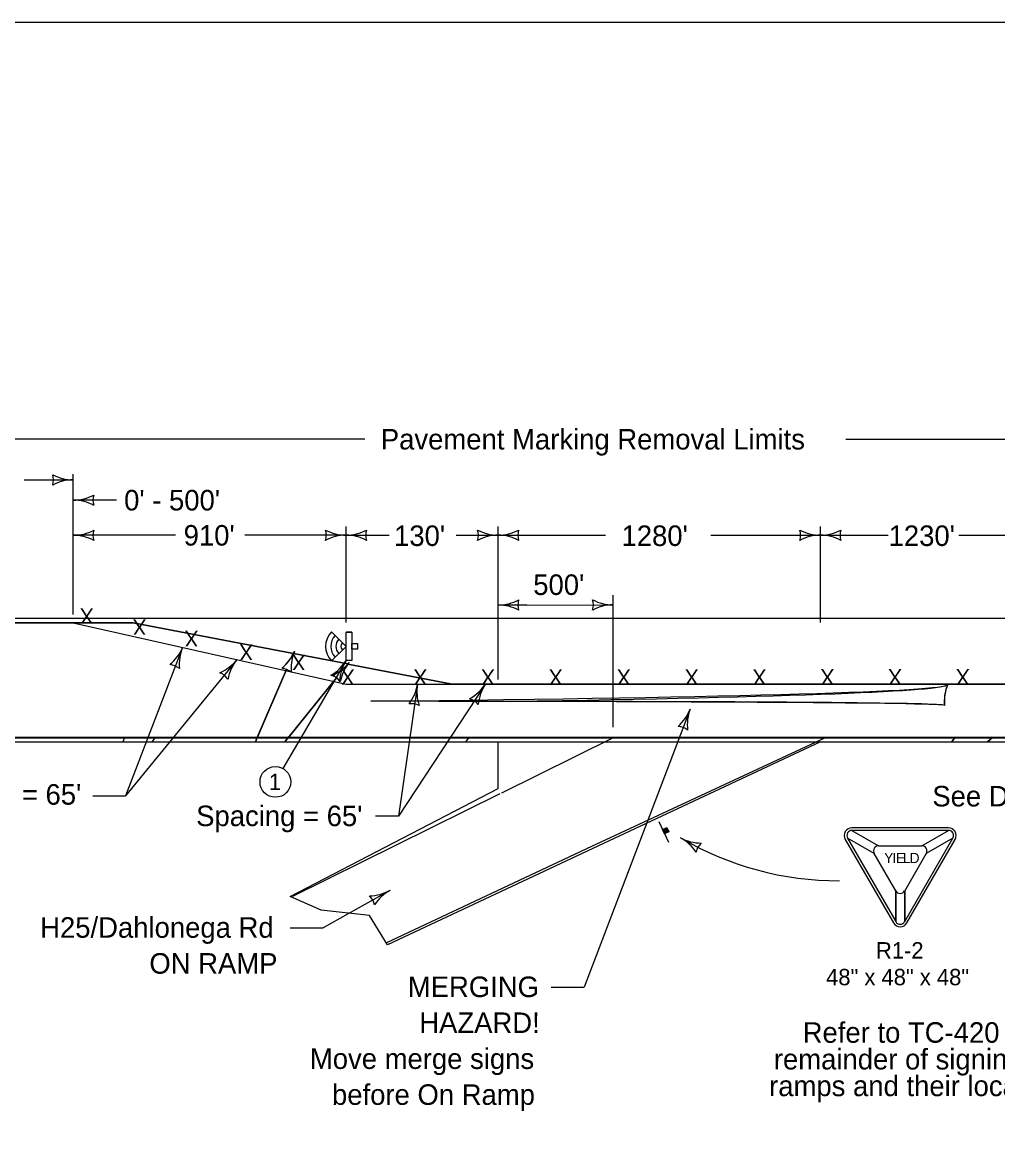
# Model space of a CAD drawing. Extents: x 10133 to 2270741, y 5363 to 1733450.
# Drawn here: x 25709 to 26660, y 8863 to 9944 of the extents above; entities that cross this region are included whole.
import ezdxf

# ---------------------------------------------------------------- set-up
doc = ezdxf.new("R2010")
doc.units = 0
for name, color, linetype in [('dsnNonPlotable', 7, 'Continuous'), ('dsnShtPlotShapeBatchPrint', 7, 'Continuous'), ('dsnStdBlockModified', 7, 'Continuous'), ('dsnStdBorder', 7, 'Continuous'), ('Level 12', 7, 'Continuous'), ('Level 2', 7, 'Continuous'), ('SheetBorder', 7, 'Continuous')]:
    doc.layers.add(name, color=color, linetype=linetype)

msp = doc.modelspace()

# ---------------------------------------------------------------- linework, layer by layer
at = {"layer": 'dsnNonPlotable'}
for p, q in [((24562.7, 9359.1), (25758.9, 9359.1)), ((25758.9, 9359.1), (26024.7, 9299.3)), ((26024.7, 9299.3), (26682.4, 9299.3)), ((24554.7, 9247), (26172.9, 9247)), ((26172.9, 9247), (26285, 9247)), ((26285, 9247), (26176.2, 9193.1)), ((26491.2, 9247), (26681.3, 9247)), ((26174.7, 9192.4), (25972.7, 9092.3))]:
    msp.add_line(p, q, dxfattribs=at)
msp.add_lwpolyline([(26063.8, 9047.3), (26264.1, 9141.5), (26491.2, 9247)], dxfattribs=at)
at = {"layer": 'dsnShtPlotShapeBatchPrint'}
msp.add_circle((25955.9, 9204), 15, dxfattribs=at)
at = {"layer": 'dsnStdBlockModified'}
for p, q in [((26010.5, 9350.1), (26024.7, 9336)), ((26030.3, 9349.7), (26024.7, 9349.7)), ((26024.7, 9336), (26010.5, 9321.8)), ((26030.3, 9322.2), (26024.7, 9322.2)), ((26329.3, 9165.5), (26338.8, 9145.3)), ((26335.3, 9153.6), (26333.3, 9157.7)), ((26333.6, 9157.8), (26335.5, 9153.7)), ((26335.7, 9153.8), (26333.8, 9157.9)), ((26333.9, 9158), (26335.9, 9153.9)), ((26336, 9153.9), (26334.1, 9158)), ((26334.3, 9158.1), (26336.2, 9154)), ((26336.4, 9154.1), (26334.5, 9158.2)), ((26334.7, 9158.3), (26336.6, 9154.2)), ((26336.8, 9154.3), (26334.9, 9158.4)), ((26335.1, 9158.5), (26337, 9154.4)), ((26337.3, 9154.5), (26335.4, 9158.6)), ((26335.7, 9158.8), (26337.6, 9154.7)), ((26337.8, 9154.8), (26335.8, 9158.9)), ((26336.2, 9159), (26338.1, 9154.9)), ((26338.3, 9155), (26336.3, 9159.1)), ((26336.6, 9159.2), (26338.5, 9155.1)), ((26338.7, 9155.2), (26336.7, 9159.3)), ((26337, 9159.4), (26338.9, 9155.3))]:
    msp.add_line(p, q, dxfattribs=at)
msp.add_lwpolyline([(26335, 9153.5), (26333.1, 9157.6), (26337.2, 9159.5), (26339.2, 9155.4)], close=True, dxfattribs=at)
for radius, start, end in [(20.3, 135.88, 224.0313), (15.3, 136.1665, 223.7159), (10.3, 136.7294, 223.0963), (5.32, 138.7005, 221.2995)]:
    msp.add_arc((26025.1, 9336), radius, start, end, dxfattribs=at)
at = {"layer": 'dsnStdBorder'}
for p, q in [((26030.3, 9349.7), (26030.3, 9322.2)), ((26611.6, 9159.3), (26517.6, 9159.3)), ((26511.1, 9148), (26558.1, 9066.6)), ((26571.1, 9066.6), (26618.1, 9148)), ((26560.3, 9097.9), (26560.3, 9067.9)), ((26569, 9067.9), (26569, 9097.9))]:
    msp.add_line(p, q, dxfattribs=at)
for points in [[(26024.7, 9322.2), (26024.7, 9349.7), (26030.3, 9349.7), (26030.3, 9322.2)], [(26030.3, 9333.3), (26030.3, 9338.9), (26035.9, 9338.9), (26035.9, 9333.3)], [(26611.6, 9156.8), (26517.6, 9156.8), (26543.6, 9141.8), (26585.7, 9141.8), (26611.6, 9156.8)], [(26513.3, 9149.3), (26560.3, 9067.9), (26560.3, 9097.9), (26539.3, 9134.3), (26513.3, 9149.3)], [(26569, 9067.9), (26616, 9149.3), (26590, 9134.3), (26569, 9097.9), (26569, 9067.9)]]:
    msp.add_lwpolyline(points, close=True, dxfattribs=at)
for centre, radius, start, end in [((26517.6, 9151.8), 7.5, 90.0002, 209.9999), ((26517.6, 9151.8), 5, 89.9999, 210.0002), ((26517.6, 9151.8), 5, 89.9999, 210.0002), ((26611.6, 9151.8), 7.5, 330.0002, 89.9999), ((26611.6, 9151.8), 5, 330.0002, 89.9999), ((26611.6, 9151.8), 5, 330.0002, 89.9999), ((26543.6, 9136.8), 5, 90.0002, 209.9999), ((26543.6, 9136.8), 5, 90.0002, 209.9999), ((26585.7, 9136.8), 5, 330.0002, 89.9999), ((26585.7, 9136.8), 5, 330.0002, 89.9999), ((26564.6, 9100.4), 5, 209.9999, 330.0002), ((26564.6, 9070.4), 7.5, 209.9999, 330.0002), ((26564.6, 9070.4), 5, 210.0002, 330.0016)]:
    msp.add_arc(centre, radius, start, end, dxfattribs=at)
at = {"layer": 'Level 12'}
for p, q in [((26043, 9537.8), (25615.3, 9537.8)), ((26511.5, 9537.8), (26932.4, 9537.8)), ((25758.9, 9367.2), (25758.9, 9503.9)), ((25711.1, 9498.3), (25758.9, 9498.3)), ((25801.2, 9478.4), (25758.9, 9478.4)), ((26024.7, 9359.3), (26024.7, 9452.9)), ((26172.9, 9303.8), (26172.9, 9452.9)), ((26486.8, 9359.3), (26486.8, 9452.9)), ((25858.5, 9444.3), (25758.9, 9444.2)), ((26024.7, 9444.3), (25926.1, 9444.3)), ((26024.7, 9444.3), (26066.8, 9444.3)), ((26132, 9444.3), (26172.9, 9444.3)), ((26172.9, 9444.3), (26277.5, 9444.3)), ((26380.1, 9444.3), (26486.8, 9444.3)), ((26486.8, 9444.3), (26552.8, 9444.3)), ((26621.7, 9444.3), (26682.5, 9444.3)), ((26285, 9257.2), (26285, 9386)), ((26200.9, 9376.3), (26172.9, 9376.3)), ((26200.9, 9376.3), (26285, 9376.4)), ((25865.4, 9334.8), (25809.9, 9190.3)), ((25918.2, 9322.9), (25809.9, 9190.3)), ((26024.7, 9322.2), (25963, 9217.2)), ((26160.2, 9298.9), (26075.9, 9170.6)), ((26094.3, 9298.9), (26075.9, 9170.6)), ((26360, 9275), (26256.7, 9004.2)), ((25777.9, 9190.3), (25809.9, 9190.3)), ((26075.9, 9170.6), (26053.4, 9170.6)), ((26067.5, 9098.3), (26002.3, 9062)), ((25970.3, 9062), (26002.3, 9062)), ((26224.7, 9004.2), (26256.7, 9004.2))]:
    msp.add_line(p, q, dxfattribs=at)
for centre, radius, start, end in [((25723.3, 9498.2), 16.4, 342.2666, 17.7334), ((25758.9, 9540.7), 42.5, 241.9275, 270), ((25758.9, 9455.7), 42.5, 90, 118.0725), ((25758.9, 9520.9), 42.5, 270, 298.0725), ((25794.5, 9478.4), 16.4, 162.2666, 197.7334), ((25758.9, 9435.9), 42.5, 61.9275, 90), ((25758.9, 9486.7), 42.5, 270, 298.0725), ((25794.5, 9444.2), 16.4, 162.2666, 197.7334), ((25989, 9444.3), 16.4, 342.2666, 17.7334), ((26024.7, 9486.8), 42.5, 241.9275, 270), ((26024.7, 9486.8), 42.5, 270, 298.0725), ((26060.3, 9444.3), 16.4, 162.2666, 197.7334), ((26137.2, 9444.3), 16.4, 342.2666, 17.7334), ((26172.9, 9486.8), 42.5, 241.9275, 270), ((26172.9, 9486.8), 42.5, 270, 298.0725), ((26208.5, 9444.3), 16.4, 162.2666, 197.7334), ((26451.2, 9444.3), 16.4, 342.2666, 17.7334), ((26486.8, 9486.8), 42.5, 241.9275, 270), ((26486.8, 9486.8), 42.5, 270, 298.0725), ((26522.4, 9444.3), 16.4, 162.2666, 197.7334), ((25758.9, 9401.7), 42.5, 61.9275, 90), ((26024.7, 9401.8), 42.5, 90, 118.0725), ((26024.7, 9401.8), 42.5, 61.9275, 90), ((26172.9, 9401.8), 42.5, 90, 118.0725), ((26172.9, 9401.8), 42.5, 61.9275, 90), ((26486.8, 9401.8), 42.5, 90, 118.0725), ((26486.8, 9401.8), 42.5, 61.9275, 90), ((26172.9, 9418.8), 42.5, 270, 298.0725), ((26172.9, 9333.8), 42.5, 61.9275, 90), ((26208.5, 9376.3), 16.4, 162.2666, 197.7334), ((26249.3, 9376.4), 16.4, 342.2666, 17.7333), ((26285, 9418.9), 42.5, 241.9275, 270), ((26285, 9333.9), 42.5, 90, 118.0725), ((25826.2, 9351.2), 42.5, 309.2655, 337.338), ((25904.7, 9318.4), 42.5, 157.338, 185.4105), ((25851.7, 9301.9), 16.4, 49.6046, 85.0713), ((25885, 9349.4), 42.5, 293.3393, 321.4118), ((25951.5, 9296.4), 42.5, 141.4118, 169.4842), ((25988.5, 9344.5), 42.5, 300.2855, 328.358), ((26060.9, 9299.9), 42.5, 148.358, 176.4305), ((25896, 9295), 16.4, 33.6784, 69.1451), ((26006, 9291.9), 16.4, 40.6246, 76.0913), ((26052.3, 9305.8), 42.5, 322.5687, 350.6412), ((26136.2, 9292), 42.5, 170.6412, 198.7137), ((26124.7, 9322.3), 42.5, 298.6127, 326.6852), ((26195.8, 9275.6), 42.5, 146.6852, 174.7577), ((26140.7, 9269.1), 16.4, 38.9518, 74.4185), ((26088.5, 9263.8), 16.4, 62.9079, 98.3746), ((26320.3, 9290.1), 42.5, 311.0454, 339.1178), ((26399.7, 9259.8), 42.5, 159.1178, 187.1903), ((26347.3, 9241.7), 16.4, 51.3845, 86.8512), ((26504.7, 9412.4), 304.7, 239.624, 270.1276), ((26370.8, 9186.9), 42.5, 241.5824, 269.6549), ((26330.4, 9112.1), 42.5, 33.5099, 61.5824), ((26382, 9132.6), 16.4, 133.849, 169.3157), ((26046.8, 9135.5), 42.5, 271.0181, 299.0906), ((26036.4, 9081), 16.4, 11.3573, 46.824), ((26088.2, 9061.2), 42.5, 119.0906, 147.1631)]:
    msp.add_arc(centre, radius, start, end, dxfattribs=at)
at = {"layer": 'Level 2'}
for p, q in [((26820.3, 9363.1), (25605.9, 9363.1)), ((25817.3, 9359.1), (25605.9, 9359.1)), ((25605.9, 9359.1), (25817.3, 9359.1)), ((25973.5, 9329), (25817.3, 9359.1)), ((25817.3, 9359.1), (25973.5, 9329)), ((25973.6, 9329), (26026.4, 9318.9)), ((26026.4, 9318.9), (25973.6, 9329)), ((26026.4, 9318.8), (26128, 9299.3)), ((26128, 9299.3), (26026.4, 9318.8)), ((25938.2, 9247.1), (25966.8, 9313.6)), ((25966.8, 9313.6), (25938.2, 9247)), ((25968.2, 9247), (26015.5, 9305.4)), ((26015.5, 9305.4), (25968.2, 9247)), ((26128, 9299.3), (26656.6, 9299.3)), ((26689.4, 9299.3), (26128, 9299.3)), ((26610.8, 9298.9), (26610.2, 9297.4)), ((26656.6, 9299.3), (26689.4, 9299.3)), ((25938.2, 9247.1), (24554.7, 9247.1)), ((24558.7, 9243.1), (25965, 9243.1)), ((24558.7, 9243.1), (25936.5, 9243.1)), ((25389.4, 9247.1), (25938.2, 9247.1)), ((25809, 9247.1), (25807.4, 9243.1)), ((25807.4, 9243.1), (25835.9, 9243.1)), ((25839, 9247.1), (25809, 9247.1)), ((25835.9, 9243.1), (25839, 9247.1)), ((25936.5, 9243.1), (25938.2, 9247.1)), ((25938.2, 9247.1), (25936.5, 9243.1)), ((25936.5, 9243.1), (25965, 9243.1)), ((25968.2, 9247.1), (25938.2, 9247.1)), ((25938.2, 9247), (25968.2, 9247)), ((25968.2, 9247.1), (25965, 9243.1)), ((25965, 9243.1), (25968.2, 9247.1)), ((25965, 9243.1), (26614.8, 9243.1)), ((26617.7, 9247.1), (25968.2, 9247.1)), ((26144.2, 9247.1), (26141.2, 9243.1)), ((26141.2, 9243.1), (26691.2, 9243.1)), ((26696.3, 9247.1), (26144.2, 9247.1)), ((26172.8, 9197.6), (26172.9, 9243.1)), ((26172.9, 9243.1), (26486.8, 9243.1)), ((26486.8, 9243.1), (26265.2, 9139.2)), ((26614.8, 9243.1), (26617.7, 9247.1)), ((26617.7, 9247.1), (26614.8, 9243.1)), ((26614.8, 9243.1), (26649.7, 9243.1)), ((26654.6, 9247.1), (26617.7, 9247.1)), ((26654.6, 9247.1), (26649.7, 9243.1)), ((26649.7, 9243.1), (26654.6, 9247.1)), ((25970.4, 9092.5), (26172.8, 9197.6)), ((26265.2, 9139.2), (26065.2, 9045.2)), ((26000.6, 9078.9), (25970.4, 9092.5)), ((26047.4, 9073.9), (26000.6, 9078.9)), ((26065.2, 9045.2), (26047.4, 9073.9))]:
    msp.add_line(p, q, dxfattribs=at)
for points in [[(25974.1, 9330.4), (25974.4, 9331.2), (25974.4, 9331.2)], [(25974.1, 9330.4), (25974.1, 9330.4)], [(26026.4, 9318.8), (26026.4, 9318.9)], [(26027.2, 9319.8), (26027.6, 9320.3), (26027.6, 9320.3)], [(26610.9, 9298.9), (26610.8, 9298.9)], [(26656.6, 9299.3), (26656.6, 9299.3), (26656.9, 9299.7)], [(25968.2, 9247), (26687.3, 9247), (26685.3, 9247)], [(26649.7, 9243.1), (26686.5, 9243.1), (26727.9, 9243.1)], [(26686.7, 9247.1), (26685.8, 9247.1), (26654.6, 9247.1)]]:
    msp.add_lwpolyline(points, dxfattribs=at)
for centre, radius, start, end in [((25935.2, 9347.6), 42.5, 309.2655, 336.072), ((25935.2, 9347.6), 42.5, 309.2655, 334.0959), ((26013.7, 9314.9), 42.5, 160.5422, 185.4105), ((26013.7, 9314.9), 42.5, 160.5422, 185.4105), ((25935.2, 9347.6), 42.5, 334.0959, 336.072), ((26013.7, 9314.9), 42.5, 157.3556, 160.5422), ((26013.7, 9314.9), 42.5, 158.6034, 160.5422), ((25935.2, 9347.6), 42.5, 337.3204, 337.338), ((25994.4, 9346.8), 42.5, 293.3393, 318.8219), ((25994.4, 9346.8), 42.5, 293.3393, 318.8219), ((26060.8, 9293.8), 42.5, 143.9415, 169.4842), ((26060.8, 9293.8), 42.5, 143.9415, 169.4842), ((26060.8, 9293.8), 42.5, 141.4294, 143.9415), ((25994.4, 9346.8), 42.5, 318.8219, 320.5615), ((25994.4, 9346.8), 42.5, 321.3942, 321.4118), ((25960.7, 9298.3), 16.4, 68.0792, 85.0713), ((25960.7, 9298.3), 16.4, 49.6046, 85.0713), ((25960.7, 9298.3), 16.4, 49.6046, 68.0792), ((26005.4, 9292.5), 16.4, 51.9095, 69.1451), ((26005.4, 9292.5), 16.4, 33.6784, 69.1451), ((26005.4, 9292.5), 16.4, 33.6784, 51.9095), ((26649.1, 9282.5), 41.5, 156.7787, 185.4824), ((26650, 9282.5), 42.5, 159.4861, 185.3297), ((26650, 9282.5), 42.5, 157.2572, 157.2748), ((26691.2, 9274.6), 42.5, 143.9182, 144.4611), ((26691.2, 9274.6), 42.5, 143.9006, 143.9011), ((26622.5, 9324.7), 42.5, 323.883, 323.9006)]:
    msp.add_arc(centre, radius, start, end, dxfattribs=at)
for centre, major_axis, ratio, start_param, end_param in [((21084.7, 9331.8), (5526.2, -32.7), 0.008175, 5.82835, 6.279465), ((23054.6, 9315.4), (3556.3, -16.3), 0.011041, 5.788962, 6.278612), ((23635.2, 9266.9), (2972.6, 11.6), 0.003601, 0.004187, 0.623197), ((24369.8, 9266.1), (2238, 12.4), 0.004792, 0.005553, 0.624564)]:
    msp.add_ellipse(centre, major_axis=major_axis, ratio=ratio, start_param=start_param, end_param=end_param, dxfattribs=at)
at = {"layer": 'SheetBorder'}
msp.add_lwpolyline([(24532.5, 9944), (27667.5, 9944), (27667.5, 7924), (24532.5, 7924)], close=True, dxfattribs=at)

# ---------------------------------------------------------------- texts
at = {"layer": 'dsnShtPlotShapeBatchPrint'}
msp.add_text('1', height=16, dxfattribs=at).set_placement((25949.5, 9196))
at = {"layer": 'dsnStdBorder'}
for p in [(25778.8, 9373.1), (25830.2, 9362.4), (25880.8, 9351.2), (25934.2, 9337.9), (25985.3, 9328), (26033.1, 9313.8), (26103.8, 9313.8), (26169.7, 9313.8), (26235.7, 9313.8), (26302, 9313.8), (26368.2, 9313.8), (26434.2, 9313.8), (26500.4, 9313.9), (26566.3, 9313.9), (26632.3, 9313.9)]:
    msp.add_text('X', height=15, rotation=180, dxfattribs=at).set_placement(p)
for s, height, p in [('Y', 10, (26549, 9124.9)), ('I', 10, (26557, 9124.9)), ('E', 10, (26560.5, 9124.9)), ('L', 10, (26567.2, 9124.9)), ('D', 10, (26573.8, 9124.9)), ('R1-2', 16, (26541, 9031.9)), ('48" x 48" x 48"', 16, (26492.4, 9005.9)), ('Refer to TC-420 for', 20, (26469.6, 8949.9)), ('remainder of signings at', 20, (26441.5, 8923.9)), ('ramps and their locations.', 20, (26436.9, 8897.9))]:
    msp.add_text(s, height=height, dxfattribs=at).set_placement(p)
at = {"layer": 'Level 12'}
for s, p in [('Pavement Marking Removal Limits', (26058.6, 9527.8)), ("0' - 500'", (25808.5, 9468.4)), ("910'", (25866.5, 9434.2)), ("130'", (26071.5, 9433.8)), ("1280'", (26293.1, 9433.8)), ("1230'", (26553.3, 9433.8)), ("500'", (26207.1, 9386.1)), ("Spacing = 65'", (25604.8, 9181.8)), ("See Detail 'A'", (26595.9, 9180.1)), ("Spacing = 65'", (25878.7, 9160.9)), ('H25/Dahlonega Rd', (25726.7, 9052.2)), ('ON RAMP', (25833.1, 9017.2)), ('MERGING', (26084.9, 8994.4)), (' HAZARD!', (26088.6, 8959.4)), ('Move merge signs', (25989.5, 8924.4)), (' before On Ramp', (26003.6, 8889.4))]:
    msp.add_text(s, height=20, dxfattribs=at).set_placement(p)

doc.saveas('drawing.dxf')
